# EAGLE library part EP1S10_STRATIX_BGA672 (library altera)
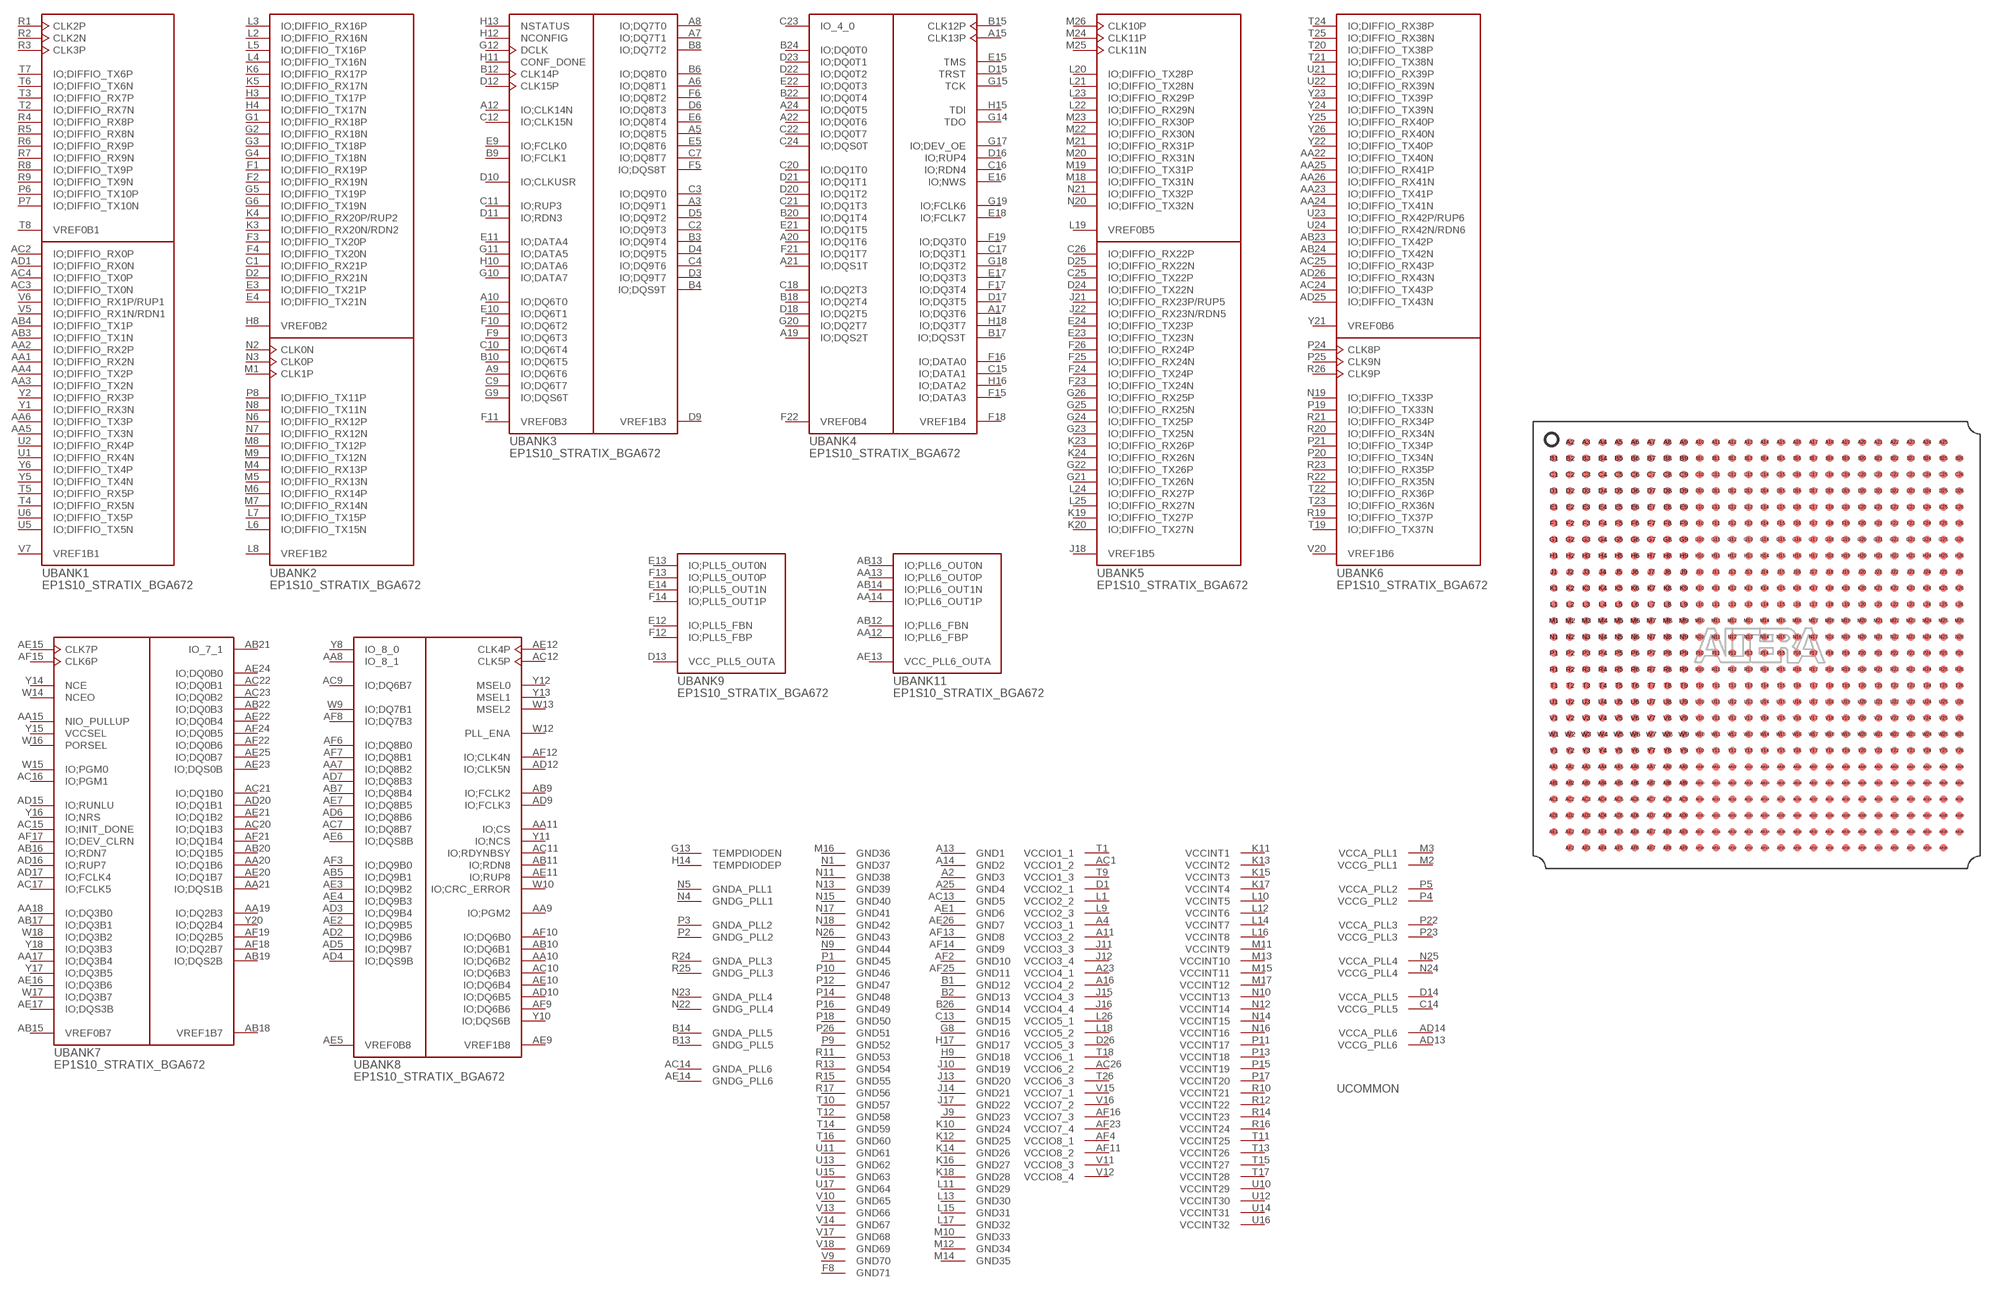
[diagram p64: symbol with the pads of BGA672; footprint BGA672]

Designator prefix -; gates COMMON=EP1S10_BGA672_0 BANK1=EP1S10_BGA672_1 BANK2=EP1S10_BGA672_2 BANK3=EP1S10_BGA672_3 BANK4=EP1S10_BGA672_4 BANK5=EP1S10_BGA672_5 BANK6=EP1S10_BGA672_6 BANK7=EP1S10_BGA672_7 BANK8=EP1S10_BGA672_8 BANK9=EP1S10_FBGA484_9 BANK11=EP1S10_FBGA484_11 NC=EP1S10_BGA672_NC

## EP1S10_STRATIX_BGA672  [BGA672]
A2  COMMON:GND3  pwr
A3  BANK3:IO;DQ9T1
A4  COMMON:VCCIO3_1  pwr
A5  BANK3:IO;DQ8T5
A6  BANK3:IO;DQ8T1
A7  BANK3:IO;DQ7T1
A8  BANK3:IO;DQ7T0
A9  BANK3:IO;DQ6T6
A10  BANK3:IO;DQ6T0
A11  COMMON:VCCIO3_2  pwr
A12  BANK3:IO;CLK14N
A13  COMMON:GND1  pwr
A14  COMMON:GND2  pwr
A15  BANK4:CLK13P  in
A16  COMMON:VCCIO4_2  pwr
A17  BANK4:IO;DQ3T6
A18  NC:P$1  nc
A19  BANK4:IO;DQS2T
A20  BANK4:IO;DQ1T6
A21  BANK4:IO;DQS1T
A22  BANK4:IO;DQ0T6
A23  COMMON:VCCIO4_1  pwr
A24  BANK4:IO;DQ0T5
A25  COMMON:GND4  pwr
AA1  BANK1:IO;DIFFIO_RX2N
AA2  BANK1:IO;DIFFIO_RX2P
AA3  BANK1:IO;DIFFIO_TX2N
AA4  BANK1:IO;DIFFIO_TX2P
AA5  BANK1:IO;DIFFIO_TX3N
AA6  BANK1:IO;DIFFIO_TX3P
AA7  BANK8:IO;DQ8B2
AA8  BANK8:IO_8_1
AA9  BANK8:IO;PGM2
AA10  BANK8:IO;DQ6B2
AA11  BANK8:IO;CS
AA12  BANK11:IO;PLL6_FBP
AA13  BANK11:IO;PLL6_OUT0P
AA14  BANK11:IO;PLL6_OUT1P
AA15  BANK7:NIO_PULLUP  in
AA16  NC:P$2  nc
AA17  BANK7:IO;DQ3B4
AA18  BANK7:IO;DQ3B0
AA19  BANK7:IO;DQ2B3
AA20  BANK7:IO;DQ1B6
AA21  BANK7:IO;DQS1B
AA22  BANK6:IO;DIFFIO_TX40N
AA23  BANK6:IO;DIFFIO_TX41P
AA24  BANK6:IO;DIFFIO_TX41N
AA25  BANK6:IO;DIFFIO_RX41P
AA26  BANK6:IO;DIFFIO_RX41N
AB1  NC:P$3  nc
AB2  NC:P$4  nc
AB3  BANK1:IO;DIFFIO_TX1N
AB4  BANK1:IO;DIFFIO_TX1P
AB5  BANK8:IO;DQ9B1
AB6  NC:P$7  nc
AB7  BANK8:IO;DQ8B4
AB8  NC:P$8  nc
AB9  BANK8:IO;FCLK2
AB10  BANK8:IO;DQ6B1
AB11  BANK8:IO;RDN8
AB12  BANK11:IO;PLL6_FBN
AB13  BANK11:IO;PLL6_OUT0N
AB14  BANK11:IO;PLL6_OUT1N
AB15  BANK7:VREF0B7  pwr
AB16  BANK7:IO;RDN7
AB17  BANK7:IO;DQ3B1
AB18  BANK7:VREF1B7  pwr
AB19  BANK7:IO;DQS2B
AB20  BANK7:IO;DQ1B5
AB21  BANK7:IO_7_1
AB22  BANK7:IO;DQ0B3
AB23  BANK6:IO;DIFFIO_TX42P
AB24  BANK6:IO;DIFFIO_TX42N
AB25  NC:P$5  nc
AB26  NC:P$6  nc
AC1  COMMON:VCCIO1_2  pwr
AC2  BANK1:IO;DIFFIO_RX0P
AC3  BANK1:IO;DIFFIO_TX0N
AC4  BANK1:IO;DIFFIO_TX0P
AC5  NC:P$11  nc
AC6  NC:P$12  nc
AC7  BANK8:IO;DQ8B7
AC8  NC:P$13  nc
AC9  BANK8:IO;DQ6B7
AC10  BANK8:IO;DQ6B3
AC11  BANK8:IO;RDYNBSY
AC12  BANK8:CLK5P  in
AC13  COMMON:GND5  pwr
AC14  COMMON:GNDA_PLL6  pwr
AC15  BANK7:IO;INIT_DONE
AC16  BANK7:IO;PGM1
AC17  BANK7:IO;FCLK5
AC18  NC:P$9  nc
AC19  NC:P$10  nc
AC20  BANK7:IO;DQ1B3
AC21  BANK7:IO;DQ1B0
AC22  BANK7:IO;DQ0B1
AC23  BANK7:IO;DQ0B2
AC24  BANK6:IO;DIFFIO_TX43P
AC25  BANK6:IO;DIFFIO_RX43P
AC26  COMMON:VCCIO6_2  pwr
AD1  BANK1:IO;DIFFIO_RX0N
AD2  BANK8:IO;DQ9B6
AD3  BANK8:IO;DQ9B4
AD4  BANK8:IO;DQS9B
AD5  BANK8:IO;DQ9B7
AD6  BANK8:IO;DQ8B6
AD7  BANK8:IO;DQ8B3
AD8  NC:P$21  nc
AD9  BANK8:IO;FCLK3
AD10  BANK8:IO;DQ6B5
AD11  NC:P$14  nc
AD12  BANK8:IO;CLK5N
AD13  COMMON:VCCG_PLL6  pwr
AD14  COMMON:VCCA_PLL6  pwr
AD15  BANK7:IO;RUNLU
AD16  BANK7:IO;RUP7
AD17  BANK7:IO;FCLK4
AD18  NC:P$15  nc
AD19  NC:P$16  nc
AD20  BANK7:IO;DQ1B1
AD21  NC:P$17  nc
AD22  NC:P$18  nc
AD23  NC:P$19  nc
AD24  NC:P$20  nc
AD25  BANK6:IO;DIFFIO_TX43N
AD26  BANK6:IO;DIFFIO_RX43N
AE1  COMMON:GND6  pwr
AE2  BANK8:IO;DQ9B5
AE3  BANK8:IO;DQ9B2
AE4  BANK8:IO;DQ9B3
AE5  BANK8:VREF0B8  pwr
AE6  BANK8:IO;DQS8B
AE7  BANK8:IO;DQ8B5
AE8  NC:P$24  nc
AE9  BANK8:VREF1B8  pwr
AE10  BANK8:IO;DQ6B4
AE11  BANK8:IO;RUP8
AE12  BANK8:CLK4P  in
AE13  BANK11:VCC_PLL6_OUTA  pwr
AE14  COMMON:GNDG_PLL6  pwr
AE15  BANK7:CLK7P  in
AE16  BANK7:IO;DQ3B6
AE17  BANK7:IO;DQS3B
AE18  NC:P$22  nc
AE19  NC:P$23  nc
AE20  BANK7:IO;DQ1B7
AE21  BANK7:IO;DQ1B2
AE22  BANK7:IO;DQ0B4
AE23  BANK7:IO;DQS0B
AE24  BANK7:IO;DQ0B0
AE25  BANK7:IO;DQ0B7
AE26  COMMON:GND7  pwr
AF2  COMMON:GND10  pwr
AF3  BANK8:IO;DQ9B0
AF4  COMMON:VCCIO8_1  pwr
AF5  NC:P$26  nc
AF6  BANK8:IO;DQ8B0
AF7  BANK8:IO;DQ8B1
AF8  BANK8:IO;DQ7B3
AF9  BANK8:IO;DQ6B6
AF10  BANK8:IO;DQ6B0
AF11  COMMON:VCCIO8_2  pwr
AF12  BANK8:IO;CLK4N
AF13  COMMON:GND8  pwr
AF14  COMMON:GND9  pwr
AF15  BANK7:CLK6P  in
AF16  COMMON:VCCIO7_3  pwr
AF17  BANK7:IO;DEV_CLRN
AF18  BANK7:IO;DQ2B7
AF19  BANK7:IO;DQ2B5
AF20  NC:P$25  nc
AF21  BANK7:IO;DQ1B4
AF22  BANK7:IO;DQ0B6
AF23  COMMON:VCCIO7_4  pwr
AF24  BANK7:IO;DQ0B5
AF25  COMMON:GND11  pwr
B1  COMMON:GND12  pwr
B2  COMMON:GND13  pwr
B3  BANK3:IO;DQ9T4
B4  BANK3:IO;DQS9T
B5  NC:P$33  nc
B6  BANK3:IO;DQ8T0
B7  NC:P$34  nc
B8  BANK3:IO;DQ7T2
B9  BANK3:IO;FCLK1
B10  BANK3:IO;DQ6T5
B11  NC:P$27  nc
B12  BANK3:CLK14P  in
B13  COMMON:GNDG_PLL5  pwr
B14  COMMON:GNDA_PLL5  pwr
B15  BANK4:CLK12P  in
B16  NC:P$28  nc
B17  BANK4:IO;DQS3T
B18  BANK4:IO;DQ2T4
B19  NC:P$29  nc
B20  BANK4:IO;DQ1T4
B21  NC:P$30  nc
B22  BANK4:IO;DQ0T4
B23  NC:P$31  nc
B24  BANK4:IO;DQ0T0
B25  NC:P$32  nc
B26  COMMON:GND14  pwr
C1  BANK2:IO;DIFFIO_RX21P
C2  BANK3:IO;DQ9T3
C3  BANK3:IO;DQ9T0
C4  BANK3:IO;DQ9T6
C5  NC:P$36  nc
C6  NC:P$37  nc
C7  BANK3:IO;DQ8T7
C8  NC:P$38  nc
C9  BANK3:IO;DQ6T7
C10  BANK3:IO;DQ6T4
C11  BANK3:IO;RUP3
C12  BANK3:IO;CLK15N
C13  COMMON:GND15  pwr
C14  COMMON:VCCG_PLL5  pwr
C15  BANK4:IO;DATA1
C16  BANK4:IO;RDN4
C17  BANK4:IO;DQ3T1
C18  BANK4:IO;DQ2T3
C19  NC:P$35  nc
C20  BANK4:IO;DQ1T0
C21  BANK4:IO;DQ1T3
C22  BANK4:IO;DQ0T7
C23  BANK4:IO_4_0
C24  BANK4:IO;DQS0T
C25  BANK5:IO;DIFFIO_TX22P
C26  BANK5:IO;DIFFIO_RX22P
D1  COMMON:VCCIO2_1  pwr
D2  BANK2:IO;DIFFIO_RX21N
D3  BANK3:IO;DQ9T7
D4  BANK3:IO;DQ9T5
D5  BANK3:IO;DQ9T2
D6  BANK3:IO;DQ8T3
D7  NC:P$40  nc
D8  NC:P$41  nc
D9  BANK3:VREF1B3  pwr
D10  BANK3:IO;CLKUSR
D11  BANK3:IO;RDN3
D12  BANK3:CLK15P  in
D13  BANK9:VCC_PLL5_OUTA  pwr
D14  COMMON:VCCA_PLL5  pwr
D15  BANK4:TRST  in
D16  BANK4:IO;RUP4
D17  BANK4:IO;DQ3T5
D18  BANK4:IO;DQ2T5
D19  NC:P$39  nc
D20  BANK4:IO;DQ1T2
D21  BANK4:IO;DQ1T1
D22  BANK4:IO;DQ0T2
D23  BANK4:IO;DQ0T1
D24  BANK5:IO;DIFFIO_TX22N
D25  BANK5:IO;DIFFIO_RX22N
D26  COMMON:VCCIO5_3  pwr
E1  NC:P$42  nc
E2  NC:P$44  nc
E3  BANK2:IO;DIFFIO_TX21P
E4  BANK2:IO;DIFFIO_TX21N
E5  BANK3:IO;DQ8T6
E6  BANK3:IO;DQ8T4
E7  NC:P$48  nc
E8  NC:P$49  nc
E9  BANK3:IO;FCLK0
E10  BANK3:IO;DQ6T1
E11  BANK3:IO;DATA4
E12  BANK9:IO;PLL5_FBN
E13  BANK9:IO;PLL5_OUT0N
E14  BANK9:IO;PLL5_OUT1N
E15  BANK4:TMS  in
E16  BANK4:IO;NWS
E17  BANK4:IO;DQ3T3
E18  BANK4:IO;FCLK7
E19  NC:P$43  nc
E20  NC:P$45  nc
E21  BANK4:IO;DQ1T5
E22  BANK4:IO;DQ0T3
E23  BANK5:IO;DIFFIO_TX23N
E24  BANK5:IO;DIFFIO_TX23P
E25  NC:P$46  nc
E26  NC:P$47  nc
F1  BANK2:IO;DIFFIO_RX19P
F2  BANK2:IO;DIFFIO_RX19N
F3  BANK2:IO;DIFFIO_TX20P
F4  BANK2:IO;DIFFIO_TX20N
F5  BANK3:IO;DQS8T
F6  BANK3:IO;DQ8T2
F7  NC:P$51  nc
F8  COMMON:GND71  pwr
F9  BANK3:IO;DQ6T3
F10  BANK3:IO;DQ6T2
F11  BANK3:VREF0B3  pwr
F12  BANK9:IO;PLL5_FBP
F13  BANK9:IO;PLL5_OUT0P
F14  BANK9:IO;PLL5_OUT1P
F15  BANK4:IO;DATA3
F16  BANK4:IO;DATA0
F17  BANK4:IO;DQ3T4
F18  BANK4:VREF1B4  pwr
F19  BANK4:IO;DQ3T0
F20  NC:P$50  nc
F21  BANK4:IO;DQ1T7
F22  BANK4:VREF0B4  pwr
F23  BANK5:IO;DIFFIO_TX24N
F24  BANK5:IO;DIFFIO_TX24P
F25  BANK5:IO;DIFFIO_RX24N
F26  BANK5:IO;DIFFIO_RX24P
G1  BANK2:IO;DIFFIO_RX18P
G2  BANK2:IO;DIFFIO_RX18N
G3  BANK2:IO;DIFFIO_TX18P
G4  BANK2:IO;DIFFIO_TX18N
G5  BANK2:IO;DIFFIO_TX19P
G6  BANK2:IO;DIFFIO_TX19N
G7  NC:P$53  nc
G8  COMMON:GND16  pwr
G9  BANK3:IO;DQS6T
G10  BANK3:IO;DATA7
G11  BANK3:IO;DATA5
G12  BANK3:DCLK  in
G13  COMMON:TEMPDIODEN  in
G14  BANK4:TDO  out
G15  BANK4:TCK  in
G16  NC:P$52  nc
G17  BANK4:IO;DEV_OE
G18  BANK4:IO;DQ3T2
G19  BANK4:IO;FCLK6
G20  BANK4:IO;DQ2T7
G21  BANK5:IO;DIFFIO_TX26N
G22  BANK5:IO;DIFFIO_TX26P
G23  BANK5:IO;DIFFIO_TX25N
G24  BANK5:IO;DIFFIO_TX25P
G25  BANK5:IO;DIFFIO_RX25N
G26  BANK5:IO;DIFFIO_RX25P
H1  NC:P$54  nc
H2  NC:P$56  nc
H3  BANK2:IO;DIFFIO_TX17P
H4  BANK2:IO;DIFFIO_TX17N
H5  NC:P$64  nc
H6  NC:P$65  nc
H7  NC:P$66  nc
H8  BANK2:VREF0B2  pwr
H9  COMMON:GND18  pwr
H10  BANK3:IO;DATA6
H11  BANK3:CONF_DONE  oc
H12  BANK3:NCONFIG  in
H13  BANK3:NSTATUS  oc
H14  COMMON:TEMPDIODEP  in
H15  BANK4:TDI  in
H16  BANK4:IO;DATA2
H17  COMMON:GND17  pwr
H18  BANK4:IO;DQ3T7
H19  NC:P$55  nc
H20  NC:P$57  nc
H21  NC:P$58  nc
H22  NC:P$59  nc
H23  NC:P$60  nc
H24  NC:P$61  nc
H25  NC:P$62  nc
H26  NC:P$63  nc
J1  NC:P$67  nc
J2  NC:P$69  nc
J3  NC:P$75  nc
J4  NC:P$76  nc
J5  NC:P$77  nc
J6  NC:P$78  nc
J7  NC:P$79  nc
J8  NC:P$80  nc
J9  COMMON:GND23  pwr
J10  COMMON:GND19  pwr
J11  COMMON:VCCIO3_3  pwr
J12  COMMON:VCCIO3_4  pwr
J13  COMMON:GND20  pwr
J14  COMMON:GND21  pwr
J15  COMMON:VCCIO4_3  pwr
J16  COMMON:VCCIO4_4  pwr
J17  COMMON:GND22  pwr
J18  BANK5:VREF1B5  pwr
J19  NC:P$68  nc
J20  NC:P$70  nc
J21  BANK5:IO;DIFFIO_RX23P/RUP5
J22  BANK5:IO;DIFFIO_RX23N/RDN5
J23  NC:P$71  nc
J24  NC:P$72  nc
J25  NC:P$73  nc
J26  NC:P$74  nc
K1  NC:P$81  nc
K2  NC:P$82  nc
K3  BANK2:IO;DIFFIO_RX20N/RDN2
K4  BANK2:IO;DIFFIO_RX20P/RUP2
K5  BANK2:IO;DIFFIO_RX17N
K6  BANK2:IO;DIFFIO_RX17P
K7  NC:P$87  nc
K8  NC:P$88  nc
K9  NC:P$89  nc
K10  COMMON:GND24  pwr
K11  COMMON:VCCINT1  pwr
K12  COMMON:GND25  pwr
K13  COMMON:VCCINT2  pwr
K14  COMMON:GND26  pwr
K15  COMMON:VCCINT3  pwr
K16  COMMON:GND27  pwr
K17  COMMON:VCCINT4  pwr
K18  COMMON:GND28  pwr
K19  BANK5:IO;DIFFIO_TX27P
K20  BANK5:IO;DIFFIO_TX27N
K21  NC:P$83  nc
K22  NC:P$84  nc
K23  BANK5:IO;DIFFIO_RX26P
K24  BANK5:IO;DIFFIO_RX26N
K25  NC:P$85  nc
K26  NC:P$86  nc
L1  COMMON:VCCIO2_2  pwr
L2  BANK2:IO;DIFFIO_RX16N
L3  BANK2:IO;DIFFIO_RX16P
L4  BANK2:IO;DIFFIO_TX16N
L5  BANK2:IO;DIFFIO_TX16P
L6  BANK2:IO;DIFFIO_TX15N
L7  BANK2:IO;DIFFIO_TX15P
L8  BANK2:VREF1B2  pwr
L9  COMMON:VCCIO2_3  pwr
L10  COMMON:VCCINT5  pwr
L11  COMMON:GND29  pwr
L12  COMMON:VCCINT6  pwr
L13  COMMON:GND30  pwr
L14  COMMON:VCCINT7  pwr
L15  COMMON:GND31  pwr
L16  COMMON:VCCINT8  pwr
L17  COMMON:GND32  pwr
L18  COMMON:VCCIO5_2  pwr
L19  BANK5:VREF0B5  pwr
L20  BANK5:IO;DIFFIO_TX28P
L21  BANK5:IO;DIFFIO_TX28N
L22  BANK5:IO;DIFFIO_RX29N
L23  BANK5:IO;DIFFIO_RX29P
L24  BANK5:IO;DIFFIO_RX27P
L25  BANK5:IO;DIFFIO_RX27N
L26  COMMON:VCCIO5_1  pwr
M1  BANK2:CLK1P  in
M2  COMMON:VCCG_PLL1  pwr
M3  COMMON:VCCA_PLL1  pwr
M4  BANK2:IO;DIFFIO_RX13P
M5  BANK2:IO;DIFFIO_RX13N
M6  BANK2:IO;DIFFIO_RX14P
M7  BANK2:IO;DIFFIO_RX14N
M8  BANK2:IO;DIFFIO_TX12P
M9  BANK2:IO;DIFFIO_TX12N
M10  COMMON:GND33  pwr
M11  COMMON:VCCINT9  pwr
M12  COMMON:GND34  pwr
M13  COMMON:VCCINT10  pwr
M14  COMMON:GND35  pwr
M15  COMMON:VCCINT11  pwr
M16  COMMON:GND36  pwr
M17  COMMON:VCCINT12  pwr
M18  BANK5:IO;DIFFIO_TX31N
M19  BANK5:IO;DIFFIO_TX31P
M20  BANK5:IO;DIFFIO_RX31N
M21  BANK5:IO;DIFFIO_RX31P
M22  BANK5:IO;DIFFIO_RX30N
M23  BANK5:IO;DIFFIO_RX30P
M24  BANK5:CLK11P  in
M25  BANK5:CLK11N
M26  BANK5:CLK10P  in
N1  COMMON:GND37  pwr
N2  BANK2:CLK0N
N3  BANK2:CLK0P  in
N4  COMMON:GNDG_PLL1  pwr
N5  COMMON:GNDA_PLL1  pwr
N6  BANK2:IO;DIFFIO_RX12P
N7  BANK2:IO;DIFFIO_RX12N
N8  BANK2:IO;DIFFIO_TX11N
N9  COMMON:GND44  pwr
N10  COMMON:VCCINT13  pwr
N11  COMMON:GND38  pwr
N12  COMMON:VCCINT14  pwr
N13  COMMON:GND39  pwr
N14  COMMON:VCCINT15  pwr
N15  COMMON:GND40  pwr
N16  COMMON:VCCINT16  pwr
N17  COMMON:GND41  pwr
N18  COMMON:GND42  pwr
N19  BANK6:IO;DIFFIO_TX33P
N20  BANK5:IO;DIFFIO_TX32N
N21  BANK5:IO;DIFFIO_TX32P
N22  COMMON:GNDG_PLL4  pwr
N23  COMMON:GNDA_PLL4  pwr
N24  COMMON:VCCG_PLL4  pwr
N25  COMMON:VCCA_PLL4  pwr
N26  COMMON:GND43  pwr
P1  COMMON:GND45  pwr
P2  COMMON:GNDG_PLL2  pwr
P3  COMMON:GNDA_PLL2  pwr
P4  COMMON:VCCG_PLL2  pwr
P5  COMMON:VCCA_PLL2  pwr
P6  BANK1:IO;DIFFIO_TX10P
P7  BANK1:IO;DIFFIO_TX10N
P8  BANK2:IO;DIFFIO_TX11P
P9  COMMON:GND52  pwr
P10  COMMON:GND46  pwr
P11  COMMON:VCCINT17  pwr
P12  COMMON:GND47  pwr
P13  COMMON:VCCINT18  pwr
P14  COMMON:GND48  pwr
P15  COMMON:VCCINT19  pwr
P16  COMMON:GND49  pwr
P17  COMMON:VCCINT20  pwr
P18  COMMON:GND50  pwr
P19  BANK6:IO;DIFFIO_TX33N
P20  BANK6:IO;DIFFIO_TX34N
P21  BANK6:IO;DIFFIO_TX34P
P22  COMMON:VCCA_PLL3  pwr
P23  COMMON:VCCG_PLL3  pwr
P24  BANK6:CLK8P  in
P25  BANK6:CLK9N
P26  COMMON:GND51  pwr
R1  BANK1:CLK2P  in
R2  BANK1:CLK2N  in
R3  BANK1:CLK3P  in
R4  BANK1:IO;DIFFIO_RX8P
R5  BANK1:IO;DIFFIO_RX8N
R6  BANK1:IO;DIFFIO_RX9P
R7  BANK1:IO;DIFFIO_RX9N
R8  BANK1:IO;DIFFIO_TX9P
R9  BANK1:IO;DIFFIO_TX9N
R10  COMMON:VCCINT21  pwr
R11  COMMON:GND53  pwr
R12  COMMON:VCCINT22  pwr
R13  COMMON:GND54  pwr
R14  COMMON:VCCINT23  pwr
R15  COMMON:GND55  pwr
R16  COMMON:VCCINT24  pwr
R17  COMMON:GND56  pwr
R18  NC:P$90  nc
R19  BANK6:IO;DIFFIO_TX37P
R20  BANK6:IO;DIFFIO_RX34N
R21  BANK6:IO;DIFFIO_RX34P
R22  BANK6:IO;DIFFIO_RX35N
R23  BANK6:IO;DIFFIO_RX35P
R24  COMMON:GNDA_PLL3  pwr
R25  COMMON:GNDG_PLL3  pwr
R26  BANK6:CLK9P  in
T1  COMMON:VCCIO1_1  pwr
T2  BANK1:IO;DIFFIO_RX7N
T3  BANK1:IO;DIFFIO_RX7P
T4  BANK1:IO;DIFFIO_RX5N
T5  BANK1:IO;DIFFIO_RX5P
T6  BANK1:IO;DIFFIO_TX6N
T7  BANK1:IO;DIFFIO_TX6P
T8  BANK1:VREF0B1  pwr
T9  COMMON:VCCIO1_3  pwr
T10  COMMON:GND57  pwr
T11  COMMON:VCCINT25  pwr
T12  COMMON:GND58  pwr
T13  COMMON:VCCINT26  pwr
T14  COMMON:GND59  pwr
T15  COMMON:VCCINT27  pwr
T16  COMMON:GND60  pwr
T17  COMMON:VCCINT28  pwr
T18  COMMON:VCCIO6_1  pwr
T19  BANK6:IO;DIFFIO_TX37N
T20  BANK6:IO;DIFFIO_TX38P
T21  BANK6:IO;DIFFIO_TX38N
T22  BANK6:IO;DIFFIO_RX36P
T23  BANK6:IO;DIFFIO_RX36N
T24  BANK6:IO;DIFFIO_RX38P
T25  BANK6:IO;DIFFIO_RX38N
T26  COMMON:VCCIO6_3  pwr
U1  BANK1:IO;DIFFIO_RX4N
U2  BANK1:IO;DIFFIO_RX4P
U3  NC:P$96  nc
U4  NC:P$97  nc
U5  BANK1:IO;DIFFIO_TX5N
U6  BANK1:IO;DIFFIO_TX5P
U7  NC:P$98  nc
U8  NC:P$99  nc
U9  NC:P$100  nc
U10  COMMON:VCCINT29  pwr
U11  COMMON:GND61  pwr
U12  COMMON:VCCINT30  pwr
U13  COMMON:GND62  pwr
U14  COMMON:VCCINT31  pwr
U15  COMMON:GND63  pwr
U16  COMMON:VCCINT32  pwr
U17  COMMON:GND64  pwr
U18  NC:P$91  nc
U19  NC:P$92  nc
U20  NC:P$93  nc
U21  BANK6:IO;DIFFIO_RX39P
U22  BANK6:IO;DIFFIO_RX39N
U23  BANK6:IO;DIFFIO_RX42P/RUP6
U24  BANK6:IO;DIFFIO_RX42N/RDN6
U25  NC:P$94  nc
U26  NC:P$95  nc
V1  NC:P$101  nc
V2  NC:P$103  nc
V3  NC:P$110  nc
V4  NC:P$111  nc
V5  BANK1:IO;DIFFIO_RX1N/RDN1
V6  BANK1:IO;DIFFIO_RX1P/RUP1
V7  BANK1:VREF1B1  pwr
V8  NC:P$112  nc
V9  COMMON:GND70  pwr
V10  COMMON:GND65  pwr
V11  COMMON:VCCIO8_3  pwr
V12  COMMON:VCCIO8_4  pwr
V13  COMMON:GND66  pwr
V14  COMMON:GND67  pwr
V15  COMMON:VCCIO7_1  pwr
V16  COMMON:VCCIO7_2  pwr
V17  COMMON:GND68  pwr
V18  COMMON:GND69  pwr
V19  NC:P$102  nc
V20  BANK6:VREF1B6  pwr
V21  NC:P$104  nc
V22  NC:P$105  nc
V23  NC:P$106  nc
V24  NC:P$107  nc
V25  NC:P$108  nc
V26  NC:P$109  nc
W1  NC:P$113  nc
W2  NC:P$116  nc
W3  NC:P$124  nc
W4  NC:P$125  nc
W5  NC:P$126  nc
W6  NC:P$127  nc
W7  NC:P$128  nc
W8  NC:P$129  nc
W9  BANK8:IO;DQ7B1
W10  BANK8:IO;CRC_ERROR
W11  NC:P$114  nc
W12  BANK8:PLL_ENA  in
W13  BANK8:MSEL2  in
W14  BANK7:NCEO  out
W15  BANK7:IO;PGM0
W16  BANK7:PORSEL  in
W17  BANK7:IO;DQ3B7
W18  BANK7:IO;DQ3B2
W19  NC:P$115  nc
W20  NC:P$117  nc
W21  NC:P$118  nc
W22  NC:P$119  nc
W23  NC:P$120  nc
W24  NC:P$121  nc
W25  NC:P$122  nc
W26  NC:P$123  nc
Y1  BANK1:IO;DIFFIO_RX3N
Y2  BANK1:IO;DIFFIO_RX3P
Y3  NC:P$131  nc
Y4  NC:P$132  nc
Y5  BANK1:IO;DIFFIO_TX4N
Y6  BANK1:IO;DIFFIO_TX4P
Y7  NC:P$133  nc
Y8  BANK8:IO_8_0
Y9  NC:P$134  nc
Y10  BANK8:IO;DQS6B
Y11  BANK8:IO;NCS
Y12  BANK8:MSEL0  in
Y13  BANK8:MSEL1  in
Y14  BANK7:NCE  in
Y15  BANK7:VCCSEL  in
Y16  BANK7:IO;NRS
Y17  BANK7:IO;DQ3B5
Y18  BANK7:IO;DQ3B3
Y19  NC:P$130  nc
Y20  BANK7:IO;DQ2B4
Y21  BANK6:VREF0B6  pwr
Y22  BANK6:IO;DIFFIO_TX40P
Y23  BANK6:IO;DIFFIO_TX39P
Y24  BANK6:IO;DIFFIO_TX39N
Y25  BANK6:IO;DIFFIO_RX40P
Y26  BANK6:IO;DIFFIO_RX40N

## Footprint BGA672 (pad centres in mm)
smd 0.584 x 0.584: A2 -14.605,15.875; A3 -13.335,15.875; A4 -12.065,15.875; A5 -10.795,15.875; A6 -9.525,15.875; A7 -8.255,15.875; A8 -6.985,15.875; A9 -5.715,15.875; A10 -4.445,15.875; A11 -3.175,15.875; A12 -1.905,15.875; A13 -0.635,15.875; A14 0.635,15.875; A15 1.905,15.875; A16 3.175,15.875; A17 4.445,15.875; A18 5.715,15.875; A19 6.985,15.875; A20 8.255,15.875; A21 9.525,15.875; A22 10.795,15.875; A23 12.065,15.875; A24 13.335,15.875; A25 14.605,15.875; AA1 -15.875,-9.525; AA2 -14.605,-9.525; AA3 -13.335,-9.525; AA4 -12.065,-9.525; AA5 -10.795,-9.525; AA6 -9.525,-9.525; AA7 -8.255,-9.525; AA8 -6.985,-9.525; AA9 -5.715,-9.525; AA10 -4.445,-9.525; AA11 -3.175,-9.525; AA12 -1.905,-9.525; AA13 -0.635,-9.525; AA14 0.635,-9.525; AA15 1.905,-9.525; AA16 3.175,-9.525; AA17 4.445,-9.525; AA18 5.715,-9.525; AA19 6.985,-9.525; AA20 8.255,-9.525; AA21 9.525,-9.525; AA22 10.795,-9.525; AA23 12.065,-9.525; AA24 13.335,-9.525; AA25 14.605,-9.525; AA26 15.875,-9.525; AB1 -15.875,-10.795; AB2 -14.605,-10.795; AB3 -13.335,-10.795; AB4 -12.065,-10.795; AB5 -10.795,-10.795; AB6 -9.525,-10.795; AB7 -8.255,-10.795; AB8 -6.985,-10.795; AB9 -5.715,-10.795; AB10 -4.445,-10.795; AB11 -3.175,-10.795; AB12 -1.905,-10.795; AB13 -0.635,-10.795; AB14 0.635,-10.795; AB15 1.905,-10.795; AB16 3.175,-10.795; AB17 4.445,-10.795; AB18 5.715,-10.795; AB19 6.985,-10.795; AB20 8.255,-10.795; AB21 9.525,-10.795; AB22 10.795,-10.795; AB23 12.065,-10.795; AB24 13.335,-10.795; AB25 14.605,-10.795; AB26 15.875,-10.795; AC1 -15.875,-12.065; AC2 -14.605,-12.065; AC3 -13.335,-12.065; AC4 -12.065,-12.065; AC5 -10.795,-12.065; AC6 -9.525,-12.065; AC7 -8.255,-12.065; AC8 -6.985,-12.065; AC9 -5.715,-12.065; AC10 -4.445,-12.065; AC11 -3.175,-12.065; AC12 -1.905,-12.065; AC13 -0.635,-12.065; AC14 0.635,-12.065; AC15 1.905,-12.065; AC16 3.175,-12.065; AC17 4.445,-12.065; AC18 5.715,-12.065; AC19 6.985,-12.065; AC20 8.255,-12.065; AC21 9.525,-12.065; AC22 10.795,-12.065; AC23 12.065,-12.065; AC24 13.335,-12.065; AC25 14.605,-12.065; AC26 15.875,-12.065; AD1 -15.875,-13.335; AD2 -14.605,-13.335; AD3 -13.335,-13.335; AD4 -12.065,-13.335; AD5 -10.795,-13.335; AD6 -9.525,-13.335; AD7 -8.255,-13.335; AD8 -6.985,-13.335; AD9 -5.715,-13.335; AD10 -4.445,-13.335; AD11 -3.175,-13.335; AD12 -1.905,-13.335; AD13 -0.635,-13.335; AD14 0.635,-13.335; AD15 1.905,-13.335; AD16 3.175,-13.335; AD17 4.445,-13.335; AD18 5.715,-13.335; AD19 6.985,-13.335; AD20 8.255,-13.335; AD21 9.525,-13.335; AD22 10.795,-13.335; AD23 12.065,-13.335; AD24 13.335,-13.335; AD25 14.605,-13.335; AD26 15.875,-13.335; AE1 -15.875,-14.605; AE2 -14.605,-14.605; AE3 -13.335,-14.605; AE4 -12.065,-14.605; AE5 -10.795,-14.605; AE6 -9.525,-14.605; AE7 -8.255,-14.605; AE8 -6.985,-14.605; AE9 -5.715,-14.605; AE10 -4.445,-14.605; AE11 -3.175,-14.605; AE12 -1.905,-14.605; AE13 -0.635,-14.605; AE14 0.635,-14.605; AE15 1.905,-14.605; AE16 3.175,-14.605; AE17 4.445,-14.605; AE18 5.715,-14.605; AE19 6.985,-14.605; AE20 8.255,-14.605; AE21 9.525,-14.605; AE22 10.795,-14.605; AE23 12.065,-14.605; AE24 13.335,-14.605; AE25 14.605,-14.605; AE26 15.875,-14.605; AF2 -14.605,-15.875; AF3 -13.335,-15.875; AF4 -12.065,-15.875; AF5 -10.795,-15.875; AF6 -9.525,-15.875; AF7 -8.255,-15.875; AF8 -6.985,-15.875; AF9 -5.715,-15.875; AF10 -4.445,-15.875; AF11 -3.175,-15.875; AF12 -1.905,-15.875; AF13 -0.635,-15.875; AF14 0.635,-15.875; AF15 1.905,-15.875; AF16 3.175,-15.875; AF17 4.445,-15.875; AF18 5.715,-15.875; AF19 6.985,-15.875; AF20 8.255,-15.875; AF21 9.525,-15.875; AF22 10.795,-15.875; AF23 12.065,-15.875; AF24 13.335,-15.875; AF25 14.605,-15.875; B1 -15.875,14.605; B2 -14.605,14.605; B3 -13.335,14.605; B4 -12.065,14.605; B5 -10.795,14.605; B6 -9.525,14.605; B7 -8.255,14.605; B8 -6.985,14.605; B9 -5.715,14.605; B10 -4.445,14.605; B11 -3.175,14.605; B12 -1.905,14.605; B13 -0.635,14.605; B14 0.635,14.605; B15 1.905,14.605; B16 3.175,14.605; B17 4.445,14.605; B18 5.715,14.605; B19 6.985,14.605; B20 8.255,14.605; B21 9.525,14.605; B22 10.795,14.605; B23 12.065,14.605; B24 13.335,14.605; B25 14.605,14.605; B26 15.875,14.605; C1 -15.875,13.335; C2 -14.605,13.335; C3 -13.335,13.335; C4 -12.065,13.335; C5 -10.795,13.335; C6 -9.525,13.335; C7 -8.255,13.335; C8 -6.985,13.335; C9 -5.715,13.335; C10 -4.445,13.335; C11 -3.175,13.335; C12 -1.905,13.335; C13 -0.635,13.335; C14 0.635,13.335; C15 1.905,13.335; C16 3.175,13.335; C17 4.445,13.335; C18 5.715,13.335; C19 6.985,13.335; C20 8.255,13.335; C21 9.525,13.335; C22 10.795,13.335; C23 12.065,13.335; C24 13.335,13.335; C25 14.605,13.335; C26 15.875,13.335; D1 -15.875,12.065; D2 -14.605,12.065; D3 -13.335,12.065; D4 -12.065,12.065; D5 -10.795,12.065; D6 -9.525,12.065; D7 -8.255,12.065; D8 -6.985,12.065; D9 -5.715,12.065; D10 -4.445,12.065; D11 -3.175,12.065; D12 -1.905,12.065; D13 -0.635,12.065; D14 0.635,12.065; D15 1.905,12.065; D16 3.175,12.065; D17 4.445,12.065; D18 5.715,12.065; D19 6.985,12.065; D20 8.255,12.065; D21 9.525,12.065; D22 10.795,12.065; D23 12.065,12.065; D24 13.335,12.065; D25 14.605,12.065; D26 15.875,12.065; E1 -15.875,10.795; E2 -14.605,10.795; E3 -13.335,10.795; E4 -12.065,10.795; E5 -10.795,10.795; E6 -9.525,10.795; E7 -8.255,10.795; E8 -6.985,10.795; E9 -5.715,10.795; E10 -4.445,10.795; E11 -3.175,10.795; E12 -1.905,10.795; E13 -0.635,10.795; E14 0.635,10.795; E15 1.905,10.795; E16 3.175,10.795; E17 4.445,10.795; E18 5.715,10.795; E19 6.985,10.795; E20 8.255,10.795; E21 9.525,10.795; E22 10.795,10.795; E23 12.065,10.795; E24 13.335,10.795; E25 14.605,10.795; E26 15.875,10.795; F1 -15.875,9.525; F2 -14.605,9.525; F3 -13.335,9.525; F4 -12.065,9.525; F5 -10.795,9.525; F6 -9.525,9.525; F7 -8.255,9.525; F8 -6.985,9.525; F9 -5.715,9.525; F10 -4.445,9.525; F11 -3.175,9.525; F12 -1.905,9.525; F13 -0.635,9.525; F14 0.635,9.525; F15 1.905,9.525; F16 3.175,9.525; F17 4.445,9.525; F18 5.715,9.525; F19 6.985,9.525; F20 8.255,9.525; F21 9.525,9.525; F22 10.795,9.525; F23 12.065,9.525; F24 13.335,9.525; F25 14.605,9.525; F26 15.875,9.525; G1 -15.875,8.255; G2 -14.605,8.255; G3 -13.335,8.255; G4 -12.065,8.255; G5 -10.795,8.255; G6 -9.525,8.255; G7 -8.255,8.255; G8 -6.985,8.255; G9 -5.715,8.255; G10 -4.445,8.255; G11 -3.175,8.255; G12 -1.905,8.255; G13 -0.635,8.255; G14 0.635,8.255; G15 1.905,8.255; G16 3.175,8.255; G17 4.445,8.255; G18 5.715,8.255; G19 6.985,8.255; G20 8.255,8.255; G21 9.525,8.255; G22 10.795,8.255; G23 12.065,8.255; G24 13.335,8.255; G25 14.605,8.255; G26 15.875,8.255; H1 -15.875,6.985; H2 -14.605,6.985; H3 -13.335,6.985; H4 -12.065,6.985; H5 -10.795,6.985; H6 -9.525,6.985; H7 -8.255,6.985; H8 -6.985,6.985; H9 -5.715,6.985; H10 -4.445,6.985; H11 -3.175,6.985; H12 -1.905,6.985; H13 -0.635,6.985; H14 0.635,6.985; H15 1.905,6.985; H16 3.175,6.985; H17 4.445,6.985; H18 5.715,6.985; H19 6.985,6.985; H20 8.255,6.985; H21 9.525,6.985; H22 10.795,6.985; H23 12.065,6.985; H24 13.335,6.985; H25 14.605,6.985; H26 15.875,6.985; J1 -15.875,5.715; J2 -14.605,5.715; J3 -13.335,5.715; J4 -12.065,5.715; J5 -10.795,5.715; J6 -9.525,5.715; J7 -8.255,5.715; J8 -6.985,5.715; J9 -5.715,5.715; J10 -4.445,5.715; J11 -3.175,5.715; J12 -1.905,5.715; J13 -0.635,5.715; J14 0.635,5.715; J15 1.905,5.715; J16 3.175,5.715; J17 4.445,5.715; J18 5.715,5.715; J19 6.985,5.715; J20 8.255,5.715; J21 9.525,5.715; J22 10.795,5.715; J23 12.065,5.715; J24 13.335,5.715; J25 14.605,5.715; J26 15.875,5.715; K1 -15.875,4.445; K2 -14.605,4.445; K3 -13.335,4.445; K4 -12.065,4.445; K5 -10.795,4.445; K6 -9.525,4.445; K7 -8.255,4.445; K8 -6.985,4.445; K9 -5.715,4.445; K10 -4.445,4.445; K11 -3.175,4.445; K12 -1.905,4.445; K13 -0.635,4.445; K14 0.635,4.445; K15 1.905,4.445; K16 3.175,4.445; K17 4.445,4.445; K18 5.715,4.445; K19 6.985,4.445; K20 8.255,4.445; K21 9.525,4.445; K22 10.795,4.445; K23 12.065,4.445; K24 13.335,4.445; K25 14.605,4.445; K26 15.875,4.445; L1 -15.875,3.175; L2 -14.605,3.175; L3 -13.335,3.175; L4 -12.065,3.175; L5 -10.795,3.175; L6 -9.525,3.175; L7 -8.255,3.175; L8 -6.985,3.175; L9 -5.715,3.175; L10 -4.445,3.175; L11 -3.175,3.175; L12 -1.905,3.175; L13 -0.635,3.175; L14 0.635,3.175; L15 1.905,3.175; L16 3.175,3.175; L17 4.445,3.175; L18 5.715,3.175; L19 6.985,3.175; L20 8.255,3.175; L21 9.525,3.175; L22 10.795,3.175; L23 12.065,3.175; L24 13.335,3.175; L25 14.605,3.175; L26 15.875,3.175; M1 -15.875,1.905; M2 -14.605,1.905; M3 -13.335,1.905; M4 -12.065,1.905; M5 -10.795,1.905; M6 -9.525,1.905; M7 -8.255,1.905; M8 -6.985,1.905; M9 -5.715,1.905; M10 -4.445,1.905; M11 -3.175,1.905; M12 -1.905,1.905; M13 -0.635,1.905; M14 0.635,1.905; M15 1.905,1.905; M16 3.175,1.905; M17 4.445,1.905; M18 5.715,1.905; M19 6.985,1.905; M20 8.255,1.905; M21 9.525,1.905; M22 10.795,1.905; M23 12.065,1.905; M24 13.335,1.905; M25 14.605,1.905; M26 15.875,1.905; N1 -15.875,0.635; N2 -14.605,0.635; N3 -13.335,0.635; N4 -12.065,0.635; N5 -10.795,0.635; N6 -9.525,0.635; N7 -8.255,0.635; N8 -6.985,0.635; N9 -5.715,0.635; N10 -4.445,0.635; N11 -3.175,0.635; N12 -1.905,0.635; N13 -0.635,0.635; N14 0.635,0.635; N15 1.905,0.635; N16 3.175,0.635; N17 4.445,0.635; N18 5.715,0.635; N19 6.985,0.635; N20 8.255,0.635; N21 9.525,0.635; N22 10.795,0.635; N23 12.065,0.635; N24 13.335,0.635; N25 14.605,0.635; N26 15.875,0.635; P1 -15.875,-0.635; P2 -14.605,-0.635; P3 -13.335,-0.635; P4 -12.065,-0.635; P5 -10.795,-0.635; P6 -9.525,-0.635; P7 -8.255,-0.635; P8 -6.985,-0.635; P9 -5.715,-0.635; P10 -4.445,-0.635; P11 -3.175,-0.635; P12 -1.905,-0.635; P13 -0.635,-0.635; P14 0.635,-0.635; P15 1.905,-0.635; P16 3.175,-0.635; P17 4.445,-0.635; P18 5.715,-0.635; P19 6.985,-0.635; P20 8.255,-0.635; P21 9.525,-0.635; P22 10.795,-0.635; P23 12.065,-0.635; P24 13.335,-0.635; P25 14.605,-0.635; P26 15.875,-0.635; R1 -15.875,-1.905; R2 -14.605,-1.905; R3 -13.335,-1.905; R4 -12.065,-1.905; R5 -10.795,-1.905; R6 -9.525,-1.905; R7 -8.255,-1.905; R8 -6.985,-1.905; R9 -5.715,-1.905; R10 -4.445,-1.905; R11 -3.175,-1.905; R12 -1.905,-1.905; R13 -0.635,-1.905; R14 0.635,-1.905; R15 1.905,-1.905; R16 3.175,-1.905; R17 4.445,-1.905; R18 5.715,-1.905; R19 6.985,-1.905; R20 8.255,-1.905; R21 9.525,-1.905; R22 10.795,-1.905; R23 12.065,-1.905; R24 13.335,-1.905; R25 14.605,-1.905; R26 15.875,-1.905; T1 -15.875,-3.175; T2 -14.605,-3.175; T3 -13.335,-3.175; T4 -12.065,-3.175; T5 -10.795,-3.175; T6 -9.525,-3.175; T7 -8.255,-3.175; T8 -6.985,-3.175; T9 -5.715,-3.175; T10 -4.445,-3.175; T11 -3.175,-3.175; T12 -1.905,-3.175; T13 -0.635,-3.175; T14 0.635,-3.175; T15 1.905,-3.175; T16 3.175,-3.175; T17 4.445,-3.175; T18 5.715,-3.175; T19 6.985,-3.175; T20 8.255,-3.175; T21 9.525,-3.175; T22 10.795,-3.175; T23 12.065,-3.175; T24 13.335,-3.175; T25 14.605,-3.175; T26 15.875,-3.175; U1 -15.875,-4.445; U2 -14.605,-4.445; U3 -13.335,-4.445; U4 -12.065,-4.445; U5 -10.795,-4.445; U6 -9.525,-4.445; U7 -8.255,-4.445; U8 -6.985,-4.445; U9 -5.715,-4.445; U10 -4.445,-4.445; U11 -3.175,-4.445; U12 -1.905,-4.445; U13 -0.635,-4.445; U14 0.635,-4.445; U15 1.905,-4.445; U16 3.175,-4.445; U17 4.445,-4.445; U18 5.715,-4.445; U19 6.985,-4.445; U20 8.255,-4.445; U21 9.525,-4.445; U22 10.795,-4.445; U23 12.065,-4.445; U24 13.335,-4.445; U25 14.605,-4.445; U26 15.875,-4.445; V1 -15.875,-5.715; V2 -14.605,-5.715; V3 -13.335,-5.715; V4 -12.065,-5.715; V5 -10.795,-5.715; V6 -9.525,-5.715; V7 -8.255,-5.715; V8 -6.985,-5.715; V9 -5.715,-5.715; V10 -4.445,-5.715; V11 -3.175,-5.715; V12 -1.905,-5.715; V13 -0.635,-5.715; V14 0.635,-5.715; V15 1.905,-5.715; V16 3.175,-5.715; V17 4.445,-5.715; V18 5.715,-5.715; V19 6.985,-5.715; V20 8.255,-5.715; V21 9.525,-5.715; V22 10.795,-5.715; V23 12.065,-5.715; V24 13.335,-5.715; V25 14.605,-5.715; V26 15.875,-5.715; W1 -15.875,-6.985; W2 -14.605,-6.985; W3 -13.335,-6.985; W4 -12.065,-6.985; W5 -10.795,-6.985; W6 -9.525,-6.985; W7 -8.255,-6.985; W8 -6.985,-6.985; W9 -5.715,-6.985; W10 -4.445,-6.985; W11 -3.175,-6.985; W12 -1.905,-6.985; W13 -0.635,-6.985; W14 0.635,-6.985; W15 1.905,-6.985; W16 3.175,-6.985; W17 4.445,-6.985; W18 5.715,-6.985; W19 6.985,-6.985; W20 8.255,-6.985; W21 9.525,-6.985; W22 10.795,-6.985; W23 12.065,-6.985; W24 13.335,-6.985; W25 14.605,-6.985; W26 15.875,-6.985; Y1 -15.875,-8.255; Y2 -14.605,-8.255; Y3 -13.335,-8.255; Y4 -12.065,-8.255; Y5 -10.795,-8.255; Y6 -9.525,-8.255; Y7 -8.255,-8.255; Y8 -6.985,-8.255; Y9 -5.715,-8.255; Y10 -4.445,-8.255; Y11 -3.175,-8.255; Y12 -1.905,-8.255; Y13 -0.635,-8.255; Y14 0.635,-8.255; Y15 1.905,-8.255; Y16 3.175,-8.255; Y17 4.445,-8.255; Y18 5.715,-8.255; Y19 6.985,-8.255; Y20 8.255,-8.255; Y21 9.525,-8.255; Y22 10.795,-8.255; Y23 12.065,-8.255; Y24 13.335,-8.255; Y25 14.605,-8.255; Y26 15.875,-8.255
